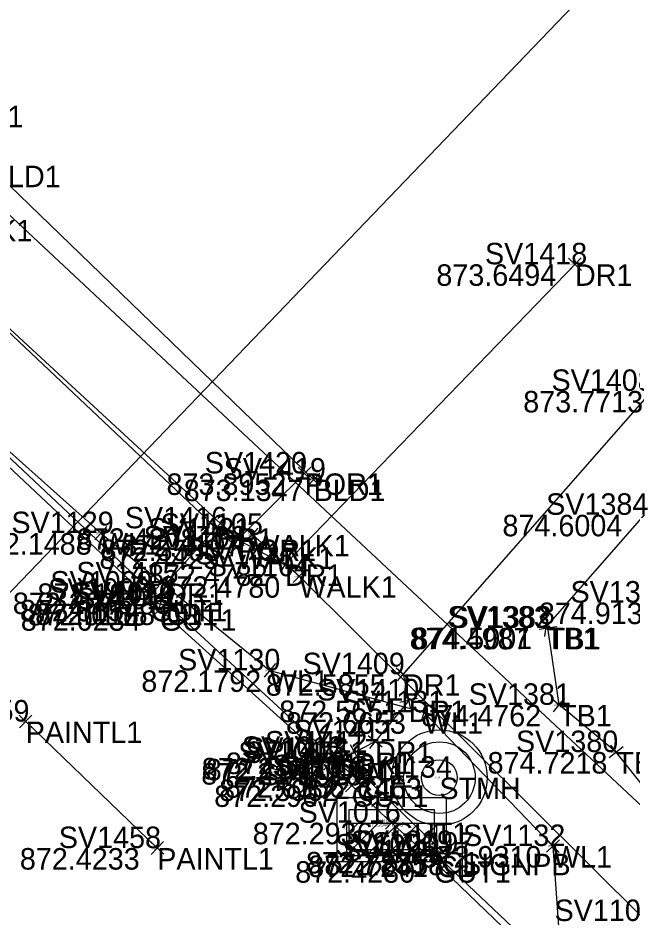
# Model space of a CAD drawing. Extents: x 1469677 to 1493262, y 375219 to 389293.
# Drawn here: x 1480097.7 to 1480132, y 379497.6 to 379547.9 of the extents above; entities that cross this region are included whole.
import ezdxf

# ---------------------------------------------------------------- set-up
doc = ezdxf.new("R2010")
doc.units = 0
for name, color, linetype in [('Border', 7, 'Continuous'), ('Building', 7, 'Continuous'), ('DR_X_Drive_Pipe', 7, 'Continuous'), ('DV_X_Lot_Line', 7, 'Continuous'), ('DV_X_Text', 7, 'Continuous'), ('GK_Visualization', 7, 'Continuous'), ('PNTELEV', 7, 'Continuous'), ('PV_X_Curb', 7, 'Continuous'), ('RD_P_Text', 7, 'Continuous'), ('RW_P_Esmt_SW', 7, 'Continuous'), ('RW_X_CL_20', 7, 'Continuous'), ('rw_x_right_of_way', 7, 'Continuous'), ('SV_X_Mon_Cells_Found', 7, 'Continuous'), ('SV_X_Random_Point', 7, 'Continuous'), ('Text Border', 7, 'Continuous'), ('UT_X_Water', 7, 'Continuous')]:
    doc.layers.add(name, color=color, linetype=linetype)

msp = doc.modelspace()

# ---------------------------------------------------------------- linework, layer by layer
at = {"layer": 'Border'}
msp.add_lwpolyline([(1480114.175, 379522.123), (1480096.037, 379539.648)], dxfattribs=at)
at = {"layer": 'Building'}
msp.add_lwpolyline([(1480105.442, 379501.552), (1480098.096, 379508.619)], dxfattribs=at)
at = {"layer": 'DR_X_Drive_Pipe'}
msp.add_lwpolyline([(1480049.152, 379568.017), (1480068.611, 379550.193), (1480086.403, 379533.424), (1480090.024, 379530.079), (1480102.295, 379519.134), (1480111.734, 379511.473), (1480120.332, 379509.136), (1480127.535, 379501.668), (1480127.911, 379496.395), (1480140.166, 379484.084), (1480149.088, 379474.708), (1480164.726, 379459.482), (1480172.622, 379452.503), (1480197.813, 379429.111)], dxfattribs=at)
at = {"layer": 'DV_X_Lot_Line'}
msp.add_lwpolyline([(1480215.341, 379421.047), (1480197.466, 379437.463), (1480177.803, 379455.97), (1480154.79, 379476.967), (1480132.747, 379497.48), (1480113.376, 379516.728), (1480110.754, 379519.04), (1480109.877, 379518.336), (1480091.944, 379535.267), (1480093.027, 379536.619), (1480090.219, 379539.243), (1480090.463, 379539.725), (1480084.681, 379544.882), (1480083.843, 379544.144), (1480066.818, 379560.524), (1480045.662, 379580.046)], dxfattribs=at)
at = {"layer": 'PNTELEV'}
for p, q in [((1480128.407, 379534.487), (1480129.126, 379533.792)), ((1480128.419, 379533.78), (1480129.114, 379534.499)), ((1480128.766, 379534.14), (1480128.766, 379534.14)), ((1480114.025, 379522.819), (1480113.314, 379522.116)), ((1480114.021, 379522.112), (1480113.317, 379522.823)), ((1480113.669, 379522.468), (1480113.669, 379522.468)), ((1480114.535, 379521.776), (1480113.816, 379522.471)), ((1480113.828, 379521.764), (1480114.523, 379522.483)), ((1480114.175, 379522.123), (1480114.175, 379522.123)), ((1480108.351, 379519.738), (1480109.093, 379519.067)), ((1480108.386, 379519.032), (1480109.057, 379519.774)), ((1480101.922, 379519.467), (1480102.668, 379518.801)), ((1480102.628, 379519.507), (1480101.962, 379518.761)), ((1480108.722, 379519.403), (1480108.722, 379519.403)), ((1480111.129, 379518.709), (1480110.379, 379519.37)), ((1480110.423, 379518.665), (1480111.084, 379519.415)), ((1480102.295, 379519.134), (1480102.295, 379519.134)), ((1480110.19, 379517.946), (1480109.564, 379518.726)), ((1480110.297, 379519.131), (1480109.586, 379518.427)), ((1480110.293, 379518.424), (1480109.59, 379519.134)), ((1480109.941, 379518.779), (1480109.941, 379518.779)), ((1480110.754, 379519.04), (1480110.754, 379519.04)), ((1480110.267, 379518.649), (1480109.487, 379518.023)), ((1480109.877, 379518.336), (1480109.877, 379518.336)), ((1480112.8, 379517.833), (1480112.336, 379516.947)), ((1480112.125, 379517.622), (1480113.011, 379517.158)), ((1480112.568, 379517.39), (1480112.568, 379517.39)), ((1480105.806, 379515.846), (1480106.075, 379516.809)), ((1480113.731, 379516.376), (1480113.021, 379517.081)), ((1480113.024, 379516.374), (1480113.728, 379517.083)), ((1480113.376, 379516.728), (1480113.376, 379516.728)), ((1480105.459, 379516.462), (1480106.422, 379516.193)), ((1480105.941, 379516.328), (1480105.941, 379516.328)), ((1480104.702, 379515.752), (1480105.431, 379515.068)), ((1480105.409, 379515.775), (1480104.725, 379515.046)), ((1480104.824, 379516.158), (1480105.553, 379515.473)), ((1480105.531, 379516.18), (1480104.846, 379515.451)), ((1480105.189, 379515.816), (1480105.189, 379515.816)), ((1480105.067, 379515.41), (1480105.067, 379515.41)), ((1480105.138, 379515.317), (1480106.101, 379515.047)), ((1480105.943, 379515.241), (1480105.235, 379514.534)), ((1480105.236, 379515.241), (1480105.943, 379514.534)), ((1480105.485, 379514.701), (1480105.755, 379515.664)), ((1480105.549, 379515.521), (1480106.324, 379514.889)), ((1480106.253, 379515.592), (1480105.621, 379514.817)), ((1480105.937, 379515.205), (1480105.937, 379515.205)), ((1480105.589, 379514.887), (1480105.589, 379514.887)), ((1480105.62, 379515.182), (1480105.62, 379515.182)), ((1480127.085, 379513.362), (1480127.21, 379514.355)), ((1480127.329, 379513.35), (1480127.186, 379514.34)), ((1480127.644, 379513.796), (1480126.652, 379513.921)), ((1480126.762, 379513.773), (1480127.752, 379513.916)), ((1480127.148, 379513.859), (1480127.148, 379513.859)), ((1480127.257, 379513.845), (1480127.257, 379513.845)), ((1480111.346, 379511.788), (1480112.123, 379511.158)), ((1480112.049, 379511.861), (1480111.419, 379511.085)), ((1480111.734, 379511.473), (1480111.734, 379511.473)), ((1480119.543, 379510.929), (1480118.792, 379511.589)), ((1480119.497, 379511.635), (1480118.837, 379510.884)), ((1480119.167, 379511.259), (1480119.167, 379511.259)), ((1480119.378, 379510.28), (1480119.589, 379509.302)), ((1480119.973, 379509.896), (1480118.995, 379509.686)), ((1480119.484, 379509.791), (1480119.484, 379509.791)), ((1480128.264, 379509.23), (1480127.492, 379509.867)), ((1480127.56, 379509.163), (1480128.196, 379509.934)), ((1480119.849, 379509.267), (1480120.814, 379509.005)), ((1480120.463, 379509.619), (1480120.2, 379508.654)), ((1480127.878, 379509.549), (1480127.878, 379509.549)), ((1480098.456, 379508.273), (1480097.735, 379508.966)), ((1480097.749, 379508.259), (1480098.442, 379508.98)), ((1480120.332, 379509.136), (1480120.332, 379509.136)), ((1480098.096, 379508.619), (1480098.096, 379508.619)), ((1480117.993, 379507.189), (1480117.22, 379507.824)), ((1480117.924, 379507.892), (1480117.289, 379507.12)), ((1480116.709, 379506.447), (1480116.23, 379507.325)), ((1480117.607, 379507.506), (1480117.607, 379507.506)), ((1480130.685, 379506.601), (1480131.466, 379507.225)), ((1480131.387, 379506.522), (1480130.764, 379507.304)), ((1480115.414, 379506.668), (1480114.743, 379505.926)), ((1480115.845, 379506.686), (1480114.893, 379506.381)), ((1480114.919, 379506.926), (1480115.655, 379506.249)), ((1480115.626, 379506.955), (1480114.948, 379506.22)), ((1480115.521, 379506.057), (1480115.216, 379507.009)), ((1480116.909, 379507.125), (1480116.031, 379506.646)), ((1480116.47, 379506.886), (1480116.47, 379506.886)), ((1480131.076, 379506.913), (1480131.076, 379506.913)), ((1480114.708, 379506.633), (1480115.449, 379505.962)), ((1480115.079, 379506.297), (1480115.079, 379506.297)), ((1480115.287, 379506.588), (1480115.287, 379506.588)), ((1480115.369, 379506.533), (1480115.369, 379506.533)), ((1480116.222, 379505.717), (1480116.953, 379505.036)), ((1480116.928, 379505.743), (1480116.247, 379505.011)), ((1480116.544, 379505.357), (1480117.455, 379505.769)), ((1480116.794, 379506.018), (1480117.205, 379505.107)), ((1480116.659, 379505.403), (1480115.947, 379504.702)), ((1480115.952, 379505.409), (1480116.654, 379504.696)), ((1480116.588, 379505.377), (1480116.588, 379505.377)), ((1480116.999, 379505.563), (1480116.999, 379505.563)), ((1480116.303, 379505.052), (1480116.303, 379505.052)), ((1480118.165, 379503.309), (1480118.895, 379502.626)), ((1480118.871, 379503.332), (1480118.188, 379502.602)), ((1480118.53, 379502.967), (1480118.53, 379502.967)), ((1480105.802, 379501.205), (1480105.082, 379501.898)), ((1480105.095, 379501.191), (1480105.789, 379501.912)), ((1480121.013, 379501.688), (1480121.732, 379500.993)), ((1480121.72, 379501.7), (1480121.025, 379500.981)), ((1480127.895, 379502.015), (1480127.175, 379501.321)), ((1480127.188, 379502.028), (1480127.882, 379501.308)), ((1480127.535, 379501.668), (1480127.535, 379501.668)), ((1480105.442, 379501.552), (1480105.442, 379501.552)), ((1480120.531, 379501.157), (1480121.272, 379500.486)), ((1480121.237, 379501.192), (1480120.566, 379500.45)), ((1480121.473, 379501.405), (1480120.632, 379500.865)), ((1480121.323, 379500.714), (1480120.783, 379501.556)), ((1480121.053, 379501.135), (1480121.053, 379501.135)), ((1480121.373, 379501.34), (1480121.373, 379501.34)), ((1480120.902, 379500.821), (1480120.902, 379500.821))]:
    msp.add_line(p, q, dxfattribs=at)
at = {"layer": 'PV_X_Curb'}
msp.add_lwpolyline([(1480139.808, 379491.765), (1480141.427, 379493.056), (1480141.937, 379493.998), (1480140.138, 379495.555), (1480131.076, 379506.913), (1480127.878, 379509.549), (1480127.257, 379513.845), (1480127.148, 379513.859), (1480132.645, 379520.158)], dxfattribs=at)
at = {"layer": 'RD_P_Text'}
for points in [[(1480043.308, 379574.086), (1480051.435, 379566.534), (1480067.64, 379551.083), (1480087.827, 379532.141), (1480105.189, 379515.816), (1480105.937, 379515.205), (1480115.287, 379506.588), (1480116.588, 379505.377), (1480116.999, 379505.563), (1480121.373, 379501.34), (1480121.053, 379501.135), (1480146.64, 379476.909), (1480171.177, 379454.102), (1480173.021, 379452.229), (1480182.175, 379443.675), (1480183.379, 379442.683), (1480186.184, 379440.013), (1480186.975, 379439.363), (1480207.407, 379420.301)], [(1480042.95, 379573.802), (1480051.182, 379566.018), (1480067.383, 379550.834), (1480087.586, 379531.809), (1480105.067, 379515.41), (1480105.589, 379514.887), (1480115.079, 379506.297), (1480116.303, 379505.052), (1480118.53, 379502.967), (1480120.902, 379500.821), (1480138.714, 379483.703), (1480170.84, 379453.681), (1480172.574, 379452.083), (1480181.867, 379443.345), (1480182.839, 379442.217), (1480185.607, 379439.661), (1480186.493, 379438.955), (1480206.919, 379419.855)]]:
    msp.add_lwpolyline(points, dxfattribs=at)
at = {"layer": 'RW_X_CL_20'}
for p, q in [((1480121.198, 379507.484), (1480121.198, 379507.484)), ((1480121.198, 379505.484), (1480121.198, 379505.484)), ((1480121.198, 379505.484), (1480121.198, 379505.484)), ((1480121.198, 379505.484), (1480121.198, 379505.484)), ((1480118.533, 379504.368), (1480118.533, 379504.368)), ((1480118.533, 379503.701), (1480118.533, 379503.701)), ((1480121.198, 379503.484), (1480121.198, 379503.484)), ((1480118.533, 379502.951), (1480118.533, 379502.951)), ((1480118.533, 379502.951), (1480118.533, 379502.951)), ((1480116.158, 379502.576), (1480116.158, 379502.576)), ((1480118.533, 379502.576), (1480118.533, 379502.576)), ((1480120.908, 379502.576), (1480120.908, 379502.576)), ((1480118.533, 379501.451), (1480118.533, 379501.451)), ((1480118.533, 379500.785), (1480118.533, 379500.785))]:
    msp.add_line(p, q, dxfattribs=at)
msp.add_circle((1480121.198, 379505.484), 2, dxfattribs=at)
at = {"layer": 'rw_x_right_of_way'}
for p, q in [((1480122.46, 379502.837), (1480122.46, 379499.637)), ((1480122.46, 379501.237), (1480120.86, 379501.237))]:
    msp.add_line(p, q, dxfattribs=at)
at = {"layer": 'SV_X_Mon_Cells_Found'}
msp.add_line((1480087.075, 379505.277), (1481914.323, 381407.96), dxfattribs=at)
msp.add_lwpolyline([(1477206.544, 382340.781), (1479657.335, 379947.979), (1480466.338, 379191.878)], dxfattribs=at)
at = {"layer": 'SV_X_Random_Point'}
for p, q in [((1480116.033, 379501.193), (1480117.787, 379502.951)), ((1480116.033, 379502.326), (1480116.657, 379502.951)), ((1480117.089, 379501.118), (1480118.917, 379502.951)), ((1480118.218, 379501.118), (1480120.047, 379502.951)), ((1480119.348, 379501.118), (1480121.033, 379502.808)), ((1480120.478, 379501.118), (1480121.033, 379501.675))]:
    msp.add_line(p, q, dxfattribs=at)
for points in [[(1480115.491, 379504.369), (1480121.575, 379504.369), (1480121.575, 379500.785), (1480115.491, 379500.785)], [(1480116.158, 379503.701), (1480120.908, 379503.701), (1480120.908, 379501.451), (1480116.158, 379501.451)], [(1480116.033, 379502.951), (1480121.033, 379502.951), (1480121.033, 379501.118), (1480116.033, 379501.118)]]:
    msp.add_lwpolyline(points, close=True, dxfattribs=at)
for radius in [2.667, 2, 1]:
    msp.add_circle((1480121.198, 379505.484), radius, dxfattribs=at)
at = {"layer": 'Text Border'}
for points in [[(1480105.62, 379515.182), (1480105.941, 379516.328), (1480108.722, 379519.403), (1480112.568, 379517.39), (1480128.766, 379534.14)], [(1480133.067, 379527.073), (1480119.167, 379511.259), (1480119.484, 379509.791), (1480117.607, 379507.506), (1480116.47, 379506.886), (1480115.369, 379506.533)]]:
    msp.add_lwpolyline(points, dxfattribs=at)
at = {"layer": 'UT_X_Water'}
msp.add_lwpolyline([(1480113.669, 379522.468), (1480109.941, 379518.779), (1480092.098, 379535.242), (1480093.306, 379536.671), (1480090.396, 379539.481), (1480093.592, 379542.995)], dxfattribs=at)

# ---------------------------------------------------------------- texts
at = {"layer": 'DV_X_Text'}
for s, height, p in [('873.6494', 1.2, (1480121.028, 379532.94)), ('873.65', 0.06, (1480128.484, 379534.08)), ('873.7713', 1.2, (1480125.878, 379525.873)), ('873.8952', 1.2, (1480105.959, 379521.268)), ('873.90', 0.06, (1480113.382, 379522.408)), ('873.1347', 1.2, (1480106.92, 379520.923)), ('873.13', 0.06, (1480113.918, 379522.063)), ('874.6004', 1.2, (1480124.718, 379518.958)), ('872.4208', 1.2, (1480100.946, 379518.203)), ('872.42', 0.06, (1480108.443, 379519.343)), ('872.1488', 1.2, (1480095.087, 379517.934)), ('872.15', 0.06, (1480102.039, 379519.074)), ('872.5583', 1.2, (1480102.279, 379517.579)), ('872.4107', 1.2, (1480103.441, 379517.84)), ('872.56', 0.06, (1480109.658, 379518.719)), ('872.41', 0.06, (1480110.497, 379518.98)), ('872.4425', 1.2, (1480102.214, 379517.136)), ('872.44', 0.06, (1480109.598, 379518.276)), ('872.4782', 1.2, (1480104.924, 379516.19)), ('872.48', 0.06, (1480112.288, 379517.33)), ('872.4780', 1.2, (1480105.619, 379515.528)), ('872.48', 0.06, (1480113.096, 379516.668)), ('872.1842', 1.2, (1480098.751, 379515.128)), ('872.18', 0.06, (1480105.685, 379516.268)), ('872.2076', 1.2, (1480097.375, 379514.616)), ('872.21', 0.06, (1480104.933, 379515.756)), ('872.0154', 1.2, (1480097.773, 379514.21)), ('872.0188', 1.2, (1480098.624, 379514.005)), ('872.02', 0.06, (1480104.783, 379515.35)), ('872.02', 0.06, (1480105.653, 379515.145)), ('874.9139', 1.2, (1480126.751, 379514.058)), ('872.0234', 1.2, (1480097.823, 379513.687)), ('872.0105', 1.2, (1480098.204, 379513.982)), ('872.02', 0.06, (1480105.305, 379514.827)), ('872.01', 0.06, (1480105.358, 379515.122)), ('874.4987', 1.2, (1480119.538, 379512.645)), ('874.5001', 1.2, (1480119.681, 379512.659)), ('874.50', 0.06, (1480126.862, 379513.799)), ('874.50', 0.06, (1480126.971, 379513.785)), ('872.1792', 1.2, (1480104.554, 379510.273)), ('872.18', 0.06, (1480111.478, 379511.413)), ('872.5855', 1.2, (1480111.505, 379510.059)), ('872.59', 0.06, (1480118.887, 379511.199)), ('872.5651', 1.2, (1480112.254, 379508.591)), ('872.57', 0.06, (1480119.205, 379509.731)), ('874.4762', 1.2, (1480120.188, 379508.349)), ('874.48', 0.06, (1480127.596, 379509.489)), ('872.6653', 1.2, (1480112.631, 379507.936)), ('872.67', 0.06, (1480120.052, 379509.076)), ('872.17', 0.06, (1480097.84, 379508.559)), ('872.4751', 1.2, (1480110.405, 379506.306)), ('872.48', 0.06, (1480117.327, 379507.446)), ('872.3178', 1.2, (1480109.271, 379505.686)), ('872.32', 0.06, (1480116.19, 379506.826)), ('874.7218', 1.2, (1480123.886, 379505.713)), ('874.72', 0.06, (1480130.797, 379506.853)), ('872.2147', 1.2, (1480107.899, 379505.097)), ('872.2106', 1.2, (1480107.927, 379505.388)), ('872.1947', 1.2, (1480108.151, 379505.333)), ('872.21', 0.06, (1480114.823, 379506.237)), ('872.21', 0.06, (1480115.031, 379506.528)), ('872.19', 0.06, (1480115.113, 379506.473)), ('872.5962', 1.2, (1480108.897, 379504.177)), ('872.6356', 1.2, (1480109.224, 379504.363)), ('872.7463', 1.2, (1480113.526, 379504.284)), ('872.60', 0.06, (1480116.303, 379505.317)), ('872.64', 0.06, (1480116.719, 379505.503)), ('872.75', 0.06, (1480120.92, 379505.424)), ('872.2967', 1.2, (1480108.622, 379503.852)), ('872.30', 0.06, (1480116.018, 379504.992)), ('872.2936', 1.2, (1480110.773, 379501.767)), ('872.2946', 0.2, (1480117.242, 379502.751)), ('872.29', 0.06, (1480118.251, 379502.907)), ('872.29', 0.01, (1480118.487, 379502.941)), ('872.9310', 1.2, (1480120.204, 379500.468)), ('872.93', 0.06, (1480127.255, 379501.608)), ('872.4233', 1.2, (1480097.77, 379500.352)), ('872.42', 0.06, (1480105.163, 379501.492)), ('872.7755', 1.2, (1480113.748, 379500.14)), ('872.7241', 1.2, (1480113.87, 379499.935)), ('872.8358', 1.2, (1480114.769, 379500.037)), ('872.72', 0.06, (1480120.775, 379501.075)), ('872.78', 0.06, (1480121.094, 379501.28)), ('872.84', 0.06, (1480122.181, 379501.177)), ('872.4280', 1.2, (1480113.145, 379499.621)), ('872.43', 0.06, (1480120.622, 379500.761))]:
    msp.add_text(s, height=height, dxfattribs=at).set_placement(p)
at = {"layer": 'GK_Visualization'}
for s, height, p in [('POR1', 1.2, (1480093.592, 379541.795)), ('BLD1', 1.2, (1480096.037, 379538.448)), ('WALK1', 1.2, (1480093.027, 379535.419)), ('DR1', 1.2, (1480128.766, 379532.94)), ('POR1', 1.2, (1480113.669, 379521.268)), ('BLD1', 1.2, (1480114.175, 379520.923)), ('DR1', 1.2, (1480108.722, 379518.203)), ('WL1', 1.2, (1480102.295, 379517.934)), ('POR1', 1.2, (1480109.941, 379517.579)), ('WALK1', 1.2, (1480110.754, 379517.84)), ('WALK1', 1.2, (1480109.877, 379517.136)), ('DR1', 1.2, (1480112.568, 379516.19)), ('WALK1', 1.2, (1480113.376, 379515.528)), ('DR1', 1.2, (1480105.941, 379515.128)), ('C1', 1.2, (1480105.189, 379514.616)), ('GUT1', 1.2, (1480105.067, 379514.21)), ('C1', 1.2, (1480105.937, 379514.005)), ('GUT1', 1.2, (1480105.589, 379513.687)), ('DR1', 1.2, (1480105.62, 379513.982)), ('TB1', 1.2, (1480127.148, 379512.659)), ('TB1', 1.2, (1480127.257, 379512.645)), ('WL1', 1.2, (1480111.734, 379510.273)), ('DR1', 1.2, (1480119.167, 379510.059)), ('DR1', 1.2, (1480119.484, 379508.591)), ('TB1', 1.2, (1480127.878, 379508.349)), ('WL1', 1.2, (1480120.332, 379507.936)), ('PAINTL1', 1.2, (1480098.096, 379507.419)), ('DR1', 1.2, (1480117.607, 379506.306)), ('DR1', 1.2, (1480116.47, 379505.686)), ('TB1', 1.2, (1480131.076, 379505.713)), ('GUT1', 1.2, (1480115.079, 379505.097)), ('C1', 1.2, (1480115.287, 379505.388)), ('DR1', 1.2, (1480115.369, 379505.333)), ('C1', 1.2, (1480116.588, 379504.177)), ('C1', 1.2, (1480116.999, 379504.363)), ('STMH', 1.2, (1480121.198, 379504.284)), ('GUT1', 1.2, (1480116.303, 379503.852)), ('CB-3', 0.2, (1480118.533, 379502.751)), ('GUT1', 1.2, (1480118.53, 379501.767)), ('WL1', 1.2, (1480127.535, 379500.468)), ('PAINTL1', 1.2, (1480105.442, 379500.352)), ('C1', 1.2, (1480121.053, 379499.935)), ('C1', 1.2, (1480121.373, 379500.14)), ('SIGNPB', 1.2, (1480122.46, 379500.037)), ('GUT1', 1.2, (1480120.902, 379499.621))]:
    msp.add_text(s, height=height, dxfattribs=at).set_placement(p)
at = {"layer": 'RW_P_Esmt_SW'}
for s, height, p in [('SV1418', 1.2, (1480123.741, 379534.14)), ('SV1418', 0.06, (1480128.515, 379534.14)), ('SV1408', 1.2, (1480127.456, 379527.073)), ('SV1420', 1.2, (1480108.095, 379522.468)), ('SV1419', 1.2, (1480109.15, 379522.123)), ('SV1420', 0.06, (1480113.39, 379522.468)), ('SV1419', 0.06, (1480113.924, 379522.123)), ('SV1384', 1.2, (1480127.156, 379520.158)), ('SV1129', 1.2, (1480097.298, 379519.134)), ('SV1416', 1.2, (1480103.63, 379519.403)), ('SV1105', 1.2, (1480105.634, 379519.04)), ('SV1421', 1.2, (1480104.923, 379518.779)), ('SV1106', 1.2, (1480104.681, 379518.336)), ('SV1416', 0.06, (1480108.467, 379519.403)), ('SV1129', 0.06, (1480102.045, 379519.134)), ('SV1421', 0.06, (1480109.69, 379518.779)), ('SV1105', 0.06, (1480110.498, 379519.04)), ('SV1417', 1.2, (1480107.552, 379517.39)), ('SV1106', 0.06, (1480109.617, 379518.336)), ('SV1104', 1.2, (1480108.266, 379516.728)), ('SV1415', 1.2, (1480100.925, 379516.328)), ('SV1417', 0.06, (1480112.317, 379517.39)), ('SV1009', 1.2, (1480099.473, 379515.816)), ('SV1104', 0.06, (1480113.12, 379516.728)), ('SV1008', 1.2, (1480099.351, 379515.41)), ('SV1414', 1.2, (1480100.614, 379515.182)), ('SV1010', 1.2, (1480100.713, 379515.205)), ('SV1415', 0.06, (1480105.69, 379516.328)), ('SV1385', 1.2, (1480128.518, 379515.258)), ('SV1011', 1.2, (1480100.921, 379514.887)), ('SV1009', 0.06, (1480104.903, 379515.816)), ('SV1008', 0.06, (1480104.781, 379515.41)), ('SV1414', 0.06, (1480105.37, 379515.182)), ('SV1010', 0.06, (1480105.676, 379515.205)), ('SV1011', 0.06, (1480105.356, 379514.887)), ('SV1383', 1.2, (1480121.65, 379513.859)), ('SV1382', 1.2, (1480121.768, 379513.845)), ('SV1383', 0.06, (1480126.873, 379513.859)), ('SV1382', 0.06, (1480126.983, 379513.845)), ('SV1130', 1.2, (1480106.605, 379511.473)), ('SV1409', 1.2, (1480113.556, 379511.259)), ('SV1130', 0.06, (1480111.478, 379511.473)), ('SV1409', 0.06, (1480118.886, 379511.259)), ('SV1410', 1.2, (1480114.364, 379509.791)), ('SV1381', 1.2, (1480122.831, 379509.549)), ('SV1131', 1.2, (1480115.758, 379509.136)), ('SV1459', 1.2, (1480092.597, 379508.619)), ('SV1410', 0.06, (1480119.228, 379509.791)), ('SV1131', 0.06, (1480120.103, 379509.136)), ('SV1381', 0.06, (1480127.626, 379509.549)), ('SV1459', 0.06, (1480097.821, 379508.619)), ('SV1411', 1.2, (1480113.042, 379507.506)), ('SV1013', 1.2, (1480110.167, 379506.588)), ('SV1413', 1.2, (1480110.353, 379506.533)), ('SV1412', 1.2, (1480111.464, 379506.886)), ('SV1380', 1.2, (1480125.473, 379506.913)), ('SV1012', 1.2, (1480109.968, 379506.297)), ('SV1411', 0.06, (1480117.379, 379507.506)), ('SV1018', 1.2, (1480111.87, 379505.563)), ('SV1412', 0.06, (1480116.22, 379506.886)), ('SV1134', 1.2, (1480116.183, 379505.484)), ('SV1380', 0.06, (1480130.796, 379506.913)), ('SV1015', 1.2, (1480111.183, 379505.052)), ('SV1014', 1.2, (1480111.477, 379505.377)), ('SV1012', 0.06, (1480114.823, 379506.297)), ('SV1013', 0.06, (1480115.031, 379506.588)), ('SV1413', 0.06, (1480115.118, 379506.533)), ('SV1014', 0.06, (1480116.332, 379505.377)), ('SV1018', 0.06, (1480116.743, 379505.563)), ('SV1134', 0.06, (1480120.947, 379505.484)), ('SV1015', 0.06, (1480116.047, 379505.052)), ('SV1016', 1.2, (1480113.334, 379502.967)), ('SV1017', 0.2, (1480117.68, 379502.951)), ('SV1458', 1.2, (1480099.944, 379501.552)), ('SV1016', 0.06, (1480118.27, 379502.967)), ('SV1017', 0.01, (1480118.49, 379502.951)), ('SV1132', 1.2, (1480122.519, 379501.668)), ('SV1020', 1.2, (1480115.375, 379501.135)), ('SV1019', 1.2, (1480116.243, 379501.34)), ('SV1197', 1.2, (1480117.435, 379501.237)), ('SV1021', 1.2, (1480115.779, 379500.821)), ('SV1132', 0.06, (1480127.284, 379501.668)), ('SV1458', 0.06, (1480105.167, 379501.552)), ('SV1020', 0.06, (1480120.769, 379501.135)), ('SV1019', 0.06, (1480121.117, 379501.34)), ('SV1197', 0.06, (1480122.209, 379501.237)), ('SV1021', 0.06, (1480120.646, 379500.821)), ('SV1103', 1.2, (1480127.627, 379497.48))]:
    msp.add_text(s, height=height, dxfattribs=at).set_placement(p)

doc.saveas('drawing.dxf')
